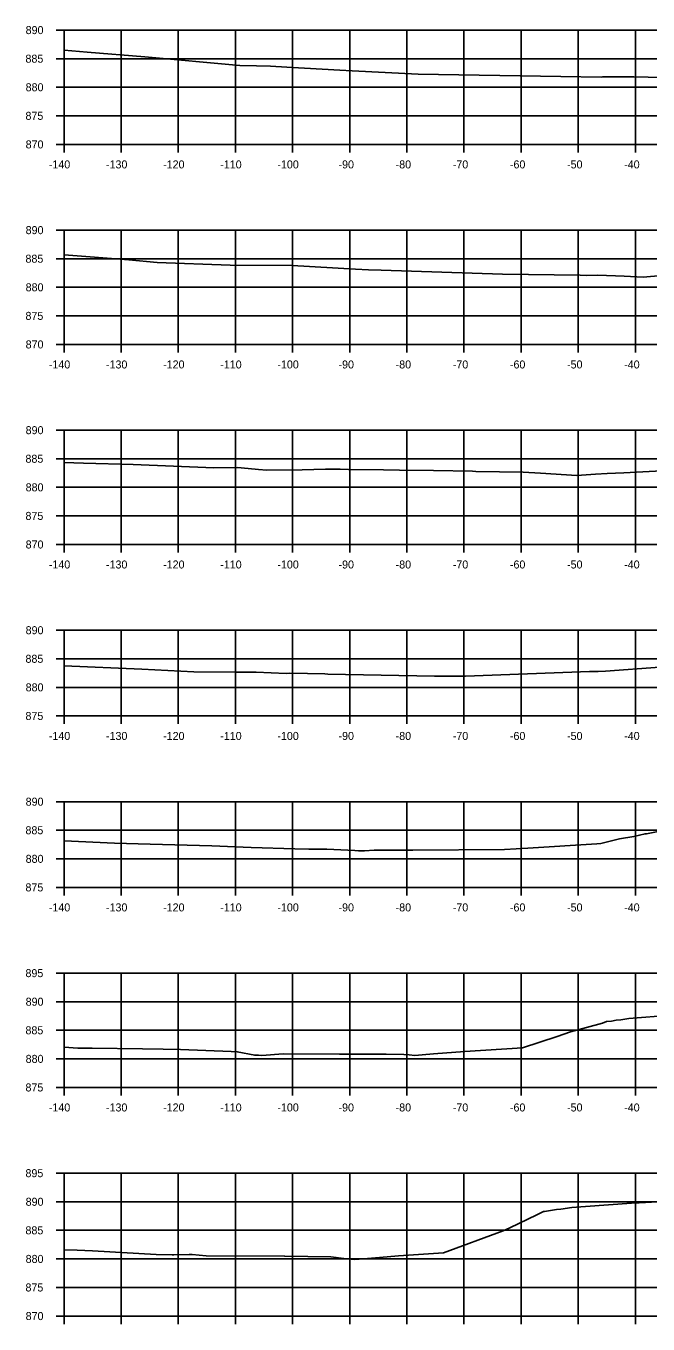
# Model space of a CAD drawing. Extents: x 1098669 to 1198896, y 698679 to 704410.
# Drawn here: x 1112162.5 to 1112271.4, y 701683.9 to 701911 of the extents above; entities that cross this region are included whole.
import ezdxf

# ---------------------------------------------------------------- set-up
doc = ezdxf.new("R2010")
doc.units = 0
for name, color, linetype in [('Proposed Surface', 7, 'Continuous'), ('R_Axis', 7, 'Continuous'), ('R_Axis Annot', 7, 'Continuous'), ('R_Grid', 7, 'Continuous')]:
    doc.layers.add(name, color=color, linetype=linetype)

msp = doc.modelspace()

# ---------------------------------------------------------------- linework, layer by layer
at = {"layer": 'Proposed Surface'}
for points in [[(1112169.18, 701906.73), (1112173.24, 701906.38), (1112183.35, 701905.57), (1112199.92, 701904.09), (1112202.88, 701903.99), (1112205.34, 701903.97), (1112208.19, 701903.8), (1112217.46, 701903.25), (1112219.61, 701903.12), (1112231.16, 701902.54), (1112256.16, 701902.15), (1112263.21, 701902.05), (1112263.45, 701902.06), (1112265.46, 701902.08), (1112268.41, 701902.11), (1112268.88, 701902.1), (1112273.92, 701901.95)], [(1112169.18, 701870.95), (1112180.51, 701870.04), (1112185.47, 701869.59), (1112198.24, 701869.14), (1112209.08, 701869.07), (1112220.21, 701868.42), (1112222.44, 701868.33), (1112224.69, 701868.27), (1112245.9, 701867.58), (1112259.5, 701867.37), (1112260.68, 701867.35), (1112262.58, 701867.38), (1112267.23, 701867.2), (1112270.55, 701867.06), (1112273.81, 701867.31)], [(1112169.18, 701834.59), (1112172.61, 701834.5), (1112181.25, 701834.23), (1112195.39, 701833.68), (1112199.52, 701833.75), (1112200.16, 701833.67), (1112203.22, 701833.4), (1112204.7, 701833.29), (1112210.83, 701833.34), (1112214.92, 701833.44), (1112217.49, 701833.41), (1112218.96, 701833.39), (1112225.12, 701833.32), (1112227.88, 701833.27), (1112233.87, 701833.2), (1112240.67, 701833.08), (1112241.27, 701833.05), (1112249.52, 701832.91), (1112252.57, 701832.74), (1112258.96, 701832.33), (1112262.22, 701832.57), (1112264.23, 701832.69), (1112267.17, 701832.8), (1112273.82, 701833.12)], [(1112169.18, 701799.04), (1112182.77, 701798.46), (1112189.63, 701798.1), (1112191.91, 701797.99), (1112199.1, 701797.93), (1112202.82, 701797.91), (1112208.04, 701797.71), (1112208.65, 701797.74), (1112211.82, 701797.67), (1112214.8, 701797.63), (1112215.37, 701797.59), (1112234.01, 701797.22), (1112239.45, 701797.23), (1112261.15, 701798.02), (1112262.64, 701798.03), (1112263.95, 701798.09), (1112273.46, 701798.77)], [(1112169.18, 701768.39), (1112178.04, 701767.98), (1112184.27, 701767.8), (1112195.07, 701767.52), (1112201.93, 701767.27), (1112209.6, 701767), (1112212.02, 701766.95), (1112215.16, 701766.96), (1112220.05, 701766.71), (1112220.74, 701766.64), (1112221.79, 701766.67), (1112223.44, 701766.78), (1112230.24, 701766.76), (1112246.3, 701766.9), (1112250.37, 701767.13), (1112262.41, 701767.91), (1112263.12, 701767.96), (1112266.41, 701768.73), (1112268.89, 701769.19), (1112270.89, 701769.65), (1112271.11, 701769.66), (1112275.15, 701770.45)], [(1112169.18, 701732.3), (1112171.62, 701732.15), (1112174.12, 701732.11), (1112182.91, 701732.02), (1112186.51, 701731.98), (1112189.54, 701731.9), (1112198.42, 701731.55), (1112199.49, 701731.51), (1112202.56, 701730.88), (1112203.19, 701730.89), (1112203.77, 701730.86), (1112207.54, 701731.12), (1112217.4, 701731.1), (1112223.28, 701731.11), (1112225.57, 701731.09), (1112228.66, 701731.04), (1112229.56, 701730.96), (1112230.56, 701730.84), (1112231.87, 701730.96), (1112233.85, 701731.15), (1112239.35, 701731.52), (1112249.41, 701732.17), (1112255.47, 701734.16), (1112257.83, 701735), (1112263.4, 701736.53), (1112264.13, 701736.8), (1112265, 701736.86), (1112265.8, 701737.01), (1112266.62, 701737.09), (1112268.06, 701737.31), (1112275.43, 701737.92)], [(1112169.18, 701696.86), (1112171.48, 701696.79), (1112174.16, 701696.65), (1112185.31, 701696.03), (1112188.12, 701695.99), (1112188.23, 701696), (1112188.37, 701696), (1112191.1, 701696.03), (1112191.57, 701696.04), (1112191.59, 701696.04), (1112191.63, 701696.03), (1112194.03, 701695.82), (1112207.78, 701695.76), (1112207.8, 701695.76), (1112207.82, 701695.76), (1112215.89, 701695.64), (1112218.18, 701695.31), (1112220.09, 701695.13), (1112221.6, 701695.25), (1112224.37, 701695.48), (1112227.7, 701695.8), (1112235.6, 701696.3), (1112246.02, 701700.19), (1112247.21, 701700.67), (1112251.91, 701702.97), (1112253.07, 701703.55), (1112253.27, 701703.58), (1112255.35, 701703.88), (1112256.11, 701703.98), (1112258.06, 701704.28), (1112260.45, 701704.44), (1112268.48, 701705), (1112269.82, 701705.06), (1112278.52, 701705.56)]]:
    msp.add_lwpolyline(points, dxfattribs=at)
at = {"layer": 'R_Axis'}
for p, q in [((1112167.78, 701910.26), (1112169.18, 701910.26)), ((1112169.18, 701890.26), (1112169.18, 701910.26)), ((1112167.78, 701905.26), (1112169.18, 701905.26)), ((1112167.78, 701900.26), (1112169.18, 701900.26)), ((1112167.78, 701895.26), (1112169.18, 701895.26)), ((1112167.78, 701890.26), (1112169.18, 701890.26)), ((1112169.18, 701890.26), (1112449.18, 701890.26)), ((1112169.18, 701888.86), (1112169.18, 701890.26)), ((1112179.18, 701888.86), (1112179.18, 701890.26)), ((1112189.18, 701888.86), (1112189.18, 701890.26)), ((1112199.18, 701888.86), (1112199.18, 701890.26)), ((1112209.18, 701888.86), (1112209.18, 701890.26)), ((1112219.18, 701888.86), (1112219.18, 701890.26)), ((1112229.18, 701888.86), (1112229.18, 701890.26)), ((1112239.18, 701888.86), (1112239.18, 701890.26)), ((1112249.18, 701888.86), (1112249.18, 701890.26)), ((1112259.18, 701888.86), (1112259.18, 701890.26)), ((1112269.18, 701888.86), (1112269.18, 701890.26)), ((1112167.78, 701875.26), (1112169.18, 701875.26)), ((1112169.18, 701855.26), (1112169.18, 701875.26)), ((1112167.78, 701870.26), (1112169.18, 701870.26)), ((1112167.78, 701865.26), (1112169.18, 701865.26)), ((1112167.78, 701860.26), (1112169.18, 701860.26)), ((1112167.78, 701855.26), (1112169.18, 701855.26)), ((1112169.18, 701855.26), (1112449.18, 701855.26)), ((1112169.18, 701853.86), (1112169.18, 701855.26)), ((1112179.18, 701853.86), (1112179.18, 701855.26)), ((1112189.18, 701853.86), (1112189.18, 701855.26)), ((1112199.18, 701853.86), (1112199.18, 701855.26)), ((1112209.18, 701853.86), (1112209.18, 701855.26)), ((1112219.18, 701853.86), (1112219.18, 701855.26)), ((1112229.18, 701853.86), (1112229.18, 701855.26)), ((1112239.18, 701853.86), (1112239.18, 701855.26)), ((1112249.18, 701853.86), (1112249.18, 701855.26)), ((1112259.18, 701853.86), (1112259.18, 701855.26)), ((1112269.18, 701853.86), (1112269.18, 701855.26)), ((1112167.78, 701840.26), (1112169.18, 701840.26)), ((1112169.18, 701820.26), (1112169.18, 701840.26)), ((1112167.78, 701835.26), (1112169.18, 701835.26)), ((1112167.78, 701830.26), (1112169.18, 701830.26)), ((1112167.78, 701825.26), (1112169.18, 701825.26)), ((1112167.78, 701820.26), (1112169.18, 701820.26)), ((1112169.18, 701820.26), (1112449.18, 701820.26)), ((1112169.18, 701818.86), (1112169.18, 701820.26)), ((1112179.18, 701818.86), (1112179.18, 701820.26)), ((1112189.18, 701818.86), (1112189.18, 701820.26)), ((1112199.18, 701818.86), (1112199.18, 701820.26)), ((1112209.18, 701818.86), (1112209.18, 701820.26)), ((1112219.18, 701818.86), (1112219.18, 701820.26)), ((1112229.18, 701818.86), (1112229.18, 701820.26)), ((1112239.18, 701818.86), (1112239.18, 701820.26)), ((1112249.18, 701818.86), (1112249.18, 701820.26)), ((1112259.18, 701818.86), (1112259.18, 701820.26)), ((1112269.18, 701818.86), (1112269.18, 701820.26)), ((1112167.78, 701805.26), (1112169.18, 701805.26)), ((1112169.18, 701790.26), (1112169.18, 701805.26)), ((1112167.78, 701800.26), (1112169.18, 701800.26)), ((1112167.78, 701795.26), (1112169.18, 701795.26)), ((1112167.78, 701790.26), (1112169.18, 701790.26)), ((1112169.18, 701790.26), (1112449.18, 701790.26)), ((1112169.18, 701788.86), (1112169.18, 701790.26)), ((1112179.18, 701788.86), (1112179.18, 701790.26)), ((1112189.18, 701788.86), (1112189.18, 701790.26)), ((1112199.18, 701788.86), (1112199.18, 701790.26)), ((1112209.18, 701788.86), (1112209.18, 701790.26)), ((1112219.18, 701788.86), (1112219.18, 701790.26)), ((1112229.18, 701788.86), (1112229.18, 701790.26)), ((1112239.18, 701788.86), (1112239.18, 701790.26)), ((1112249.18, 701788.86), (1112249.18, 701790.26)), ((1112259.18, 701788.86), (1112259.18, 701790.26)), ((1112269.18, 701788.86), (1112269.18, 701790.26)), ((1112167.78, 701775.26), (1112169.18, 701775.26)), ((1112169.18, 701760.26), (1112169.18, 701775.26)), ((1112167.78, 701770.26), (1112169.18, 701770.26)), ((1112167.78, 701765.26), (1112169.18, 701765.26)), ((1112167.78, 701760.26), (1112169.18, 701760.26)), ((1112169.18, 701760.26), (1112449.18, 701760.26)), ((1112169.18, 701758.86), (1112169.18, 701760.26)), ((1112179.18, 701758.86), (1112179.18, 701760.26)), ((1112189.18, 701758.86), (1112189.18, 701760.26)), ((1112199.18, 701758.86), (1112199.18, 701760.26)), ((1112209.18, 701758.86), (1112209.18, 701760.26)), ((1112219.18, 701758.86), (1112219.18, 701760.26)), ((1112229.18, 701758.86), (1112229.18, 701760.26)), ((1112239.18, 701758.86), (1112239.18, 701760.26)), ((1112249.18, 701758.86), (1112249.18, 701760.26)), ((1112259.18, 701758.86), (1112259.18, 701760.26)), ((1112269.18, 701758.86), (1112269.18, 701760.26)), ((1112167.78, 701745.26), (1112169.18, 701745.26)), ((1112169.18, 701725.26), (1112169.18, 701745.26)), ((1112167.78, 701740.26), (1112169.18, 701740.26)), ((1112167.78, 701735.26), (1112169.18, 701735.26)), ((1112167.78, 701730.26), (1112169.18, 701730.26)), ((1112167.78, 701725.26), (1112169.18, 701725.26)), ((1112169.18, 701725.26), (1112449.18, 701725.26)), ((1112169.18, 701723.86), (1112169.18, 701725.26)), ((1112179.18, 701723.86), (1112179.18, 701725.26)), ((1112189.18, 701723.86), (1112189.18, 701725.26)), ((1112199.18, 701723.86), (1112199.18, 701725.26)), ((1112209.18, 701723.86), (1112209.18, 701725.26)), ((1112219.18, 701723.86), (1112219.18, 701725.26)), ((1112229.18, 701723.86), (1112229.18, 701725.26)), ((1112239.18, 701723.86), (1112239.18, 701725.26)), ((1112249.18, 701723.86), (1112249.18, 701725.26)), ((1112259.18, 701723.86), (1112259.18, 701725.26)), ((1112269.18, 701723.86), (1112269.18, 701725.26)), ((1112167.78, 701710.26), (1112169.18, 701710.26)), ((1112169.18, 701685.26), (1112169.18, 701710.26)), ((1112167.78, 701705.26), (1112169.18, 701705.26)), ((1112167.78, 701700.26), (1112169.18, 701700.26)), ((1112167.78, 701695.26), (1112169.18, 701695.26)), ((1112167.78, 701690.26), (1112169.18, 701690.26)), ((1112167.78, 701685.26), (1112169.18, 701685.26)), ((1112169.18, 701685.26), (1112449.18, 701685.26)), ((1112169.18, 701683.86), (1112169.18, 701685.26)), ((1112179.18, 701683.86), (1112179.18, 701685.26)), ((1112189.18, 701683.86), (1112189.18, 701685.26)), ((1112199.18, 701683.86), (1112199.18, 701685.26)), ((1112209.18, 701683.86), (1112209.18, 701685.26)), ((1112219.18, 701683.86), (1112219.18, 701685.26)), ((1112229.18, 701683.86), (1112229.18, 701685.26)), ((1112239.18, 701683.86), (1112239.18, 701685.26)), ((1112249.18, 701683.86), (1112249.18, 701685.26)), ((1112259.18, 701683.86), (1112259.18, 701685.26)), ((1112269.18, 701683.86), (1112269.18, 701685.26))]:
    msp.add_line(p, q, dxfattribs=at)
at = {"layer": 'R_Grid'}
for p, q in [((1112169.18, 701910.26), (1112449.18, 701910.26)), ((1112169.18, 701890.26), (1112169.18, 701910.26)), ((1112179.18, 701890.26), (1112179.18, 701910.26)), ((1112189.18, 701890.26), (1112189.18, 701910.26)), ((1112199.18, 701890.26), (1112199.18, 701910.26)), ((1112209.18, 701890.26), (1112209.18, 701910.26)), ((1112219.18, 701890.26), (1112219.18, 701910.26)), ((1112229.18, 701890.26), (1112229.18, 701910.26)), ((1112239.18, 701890.26), (1112239.18, 701910.26)), ((1112249.18, 701890.26), (1112249.18, 701910.26)), ((1112259.18, 701890.26), (1112259.18, 701910.26)), ((1112269.18, 701890.26), (1112269.18, 701910.26)), ((1112169.18, 701905.26), (1112449.18, 701905.26)), ((1112169.18, 701900.26), (1112449.18, 701900.26)), ((1112169.18, 701895.26), (1112449.18, 701895.26)), ((1112169.18, 701890.26), (1112449.18, 701890.26)), ((1112169.18, 701875.26), (1112449.18, 701875.26)), ((1112169.18, 701855.26), (1112169.18, 701875.26)), ((1112179.18, 701855.26), (1112179.18, 701875.26)), ((1112189.18, 701855.26), (1112189.18, 701875.26)), ((1112199.18, 701855.26), (1112199.18, 701875.26)), ((1112209.18, 701855.26), (1112209.18, 701875.26)), ((1112219.18, 701855.26), (1112219.18, 701875.26)), ((1112229.18, 701855.26), (1112229.18, 701875.26)), ((1112239.18, 701855.26), (1112239.18, 701875.26)), ((1112249.18, 701855.26), (1112249.18, 701875.26)), ((1112259.18, 701855.26), (1112259.18, 701875.26)), ((1112269.18, 701855.26), (1112269.18, 701875.26)), ((1112169.18, 701870.26), (1112449.18, 701870.26)), ((1112169.18, 701865.26), (1112449.18, 701865.26)), ((1112169.18, 701860.26), (1112449.18, 701860.26)), ((1112169.18, 701855.26), (1112449.18, 701855.26)), ((1112169.18, 701840.26), (1112449.18, 701840.26)), ((1112169.18, 701820.26), (1112169.18, 701840.26)), ((1112179.18, 701820.26), (1112179.18, 701840.26)), ((1112189.18, 701820.26), (1112189.18, 701840.26)), ((1112199.18, 701820.26), (1112199.18, 701840.26)), ((1112209.18, 701820.26), (1112209.18, 701840.26)), ((1112219.18, 701820.26), (1112219.18, 701840.26)), ((1112229.18, 701820.26), (1112229.18, 701840.26)), ((1112239.18, 701820.26), (1112239.18, 701840.26)), ((1112249.18, 701820.26), (1112249.18, 701840.26)), ((1112259.18, 701820.26), (1112259.18, 701840.26)), ((1112269.18, 701820.26), (1112269.18, 701840.26)), ((1112169.18, 701835.26), (1112449.18, 701835.26)), ((1112169.18, 701830.26), (1112449.18, 701830.26)), ((1112169.18, 701825.26), (1112449.18, 701825.26)), ((1112169.18, 701820.26), (1112449.18, 701820.26)), ((1112169.18, 701805.26), (1112449.18, 701805.26)), ((1112169.18, 701790.26), (1112169.18, 701805.26)), ((1112179.18, 701790.26), (1112179.18, 701805.26)), ((1112189.18, 701790.26), (1112189.18, 701805.26)), ((1112199.18, 701790.26), (1112199.18, 701805.26)), ((1112209.18, 701790.26), (1112209.18, 701805.26)), ((1112219.18, 701790.26), (1112219.18, 701805.26)), ((1112229.18, 701790.26), (1112229.18, 701805.26)), ((1112239.18, 701790.26), (1112239.18, 701805.26)), ((1112249.18, 701790.26), (1112249.18, 701805.26)), ((1112259.18, 701790.26), (1112259.18, 701805.26)), ((1112269.18, 701790.26), (1112269.18, 701805.26)), ((1112169.18, 701800.26), (1112449.18, 701800.26)), ((1112169.18, 701795.26), (1112449.18, 701795.26)), ((1112169.18, 701790.26), (1112449.18, 701790.26)), ((1112169.18, 701775.26), (1112449.18, 701775.26)), ((1112169.18, 701760.26), (1112169.18, 701775.26)), ((1112179.18, 701760.26), (1112179.18, 701775.26)), ((1112189.18, 701760.26), (1112189.18, 701775.26)), ((1112199.18, 701760.26), (1112199.18, 701775.26)), ((1112209.18, 701760.26), (1112209.18, 701775.26)), ((1112219.18, 701760.26), (1112219.18, 701775.26)), ((1112229.18, 701760.26), (1112229.18, 701775.26)), ((1112239.18, 701760.26), (1112239.18, 701775.26)), ((1112249.18, 701760.26), (1112249.18, 701775.26)), ((1112259.18, 701760.26), (1112259.18, 701775.26)), ((1112269.18, 701760.26), (1112269.18, 701775.26)), ((1112169.18, 701770.26), (1112449.18, 701770.26)), ((1112169.18, 701765.26), (1112449.18, 701765.26)), ((1112169.18, 701760.26), (1112449.18, 701760.26)), ((1112169.18, 701745.26), (1112449.18, 701745.26)), ((1112169.18, 701725.26), (1112169.18, 701745.26)), ((1112179.18, 701725.26), (1112179.18, 701745.26)), ((1112189.18, 701725.26), (1112189.18, 701745.26)), ((1112199.18, 701725.26), (1112199.18, 701745.26)), ((1112209.18, 701725.26), (1112209.18, 701745.26)), ((1112219.18, 701725.26), (1112219.18, 701745.26)), ((1112229.18, 701725.26), (1112229.18, 701745.26)), ((1112239.18, 701725.26), (1112239.18, 701745.26)), ((1112249.18, 701725.26), (1112249.18, 701745.26)), ((1112259.18, 701725.26), (1112259.18, 701745.26)), ((1112269.18, 701725.26), (1112269.18, 701745.26)), ((1112169.18, 701740.26), (1112449.18, 701740.26)), ((1112169.18, 701735.26), (1112449.18, 701735.26)), ((1112169.18, 701730.26), (1112449.18, 701730.26)), ((1112169.18, 701725.26), (1112449.18, 701725.26)), ((1112169.18, 701710.26), (1112449.18, 701710.26)), ((1112169.18, 701685.26), (1112169.18, 701710.26)), ((1112179.18, 701685.26), (1112179.18, 701710.26)), ((1112189.18, 701685.26), (1112189.18, 701710.26)), ((1112199.18, 701685.26), (1112199.18, 701710.26)), ((1112209.18, 701685.26), (1112209.18, 701710.26)), ((1112219.18, 701685.26), (1112219.18, 701710.26)), ((1112229.18, 701685.26), (1112229.18, 701710.26)), ((1112239.18, 701685.26), (1112239.18, 701710.26)), ((1112249.18, 701685.26), (1112249.18, 701710.26)), ((1112259.18, 701685.26), (1112259.18, 701710.26)), ((1112269.18, 701685.26), (1112269.18, 701710.26)), ((1112169.18, 701705.26), (1112449.18, 701705.26)), ((1112169.18, 701700.26), (1112449.18, 701700.26)), ((1112169.18, 701695.26), (1112449.18, 701695.26)), ((1112169.18, 701690.26), (1112449.18, 701690.26)), ((1112169.18, 701685.26), (1112449.18, 701685.26))]:
    msp.add_line(p, q, dxfattribs=at)

# ---------------------------------------------------------------- texts
at = {"layer": 'R_Axis Annot'}
for s, p in [('890', (1112162.46, 701909.56)), ('885', (1112162.43, 701904.56)), ('880', (1112162.46, 701899.56)), ('875', (1112162.43, 701894.56)), ('870', (1112162.46, 701889.56)), ('-140', (1112166.52, 701886.06)), ('-130', (1112176.52, 701886.06)), ('-120', (1112186.52, 701886.06)), ('-110', (1112196.52, 701886.06)), ('-100', (1112206.52, 701886.06)), ('-90', (1112217.22, 701886.06)), ('-80', (1112227.22, 701886.06)), ('-70', (1112237.22, 701886.06)), ('-60', (1112247.22, 701886.06)), ('-50', (1112257.22, 701886.06)), ('-40', (1112267.22, 701886.06)), ('890', (1112162.46, 701874.56)), ('885', (1112162.43, 701869.56)), ('880', (1112162.46, 701864.56)), ('875', (1112162.43, 701859.56)), ('870', (1112162.46, 701854.56)), ('-140', (1112166.52, 701851.06)), ('-130', (1112176.52, 701851.06)), ('-120', (1112186.52, 701851.06)), ('-110', (1112196.52, 701851.06)), ('-100', (1112206.52, 701851.06)), ('-90', (1112217.22, 701851.06)), ('-80', (1112227.22, 701851.06)), ('-70', (1112237.22, 701851.06)), ('-60', (1112247.22, 701851.06)), ('-50', (1112257.22, 701851.06)), ('-40', (1112267.22, 701851.06)), ('890', (1112162.46, 701839.56)), ('885', (1112162.43, 701834.56)), ('880', (1112162.46, 701829.56)), ('875', (1112162.43, 701824.56)), ('870', (1112162.46, 701819.56)), ('-140', (1112166.52, 701816.06)), ('-130', (1112176.52, 701816.06)), ('-120', (1112186.52, 701816.06)), ('-110', (1112196.52, 701816.06)), ('-100', (1112206.52, 701816.06)), ('-90', (1112217.22, 701816.06)), ('-80', (1112227.22, 701816.06)), ('-70', (1112237.22, 701816.06)), ('-60', (1112247.22, 701816.06)), ('-50', (1112257.22, 701816.06)), ('-40', (1112267.22, 701816.06)), ('890', (1112162.46, 701804.56)), ('885', (1112162.43, 701799.56)), ('880', (1112162.46, 701794.56)), ('875', (1112162.43, 701789.56)), ('-140', (1112166.52, 701786.06)), ('-130', (1112176.52, 701786.06)), ('-120', (1112186.52, 701786.06)), ('-110', (1112196.52, 701786.06)), ('-100', (1112206.52, 701786.06)), ('-90', (1112217.22, 701786.06)), ('-80', (1112227.22, 701786.06)), ('-70', (1112237.22, 701786.06)), ('-60', (1112247.22, 701786.06)), ('-50', (1112257.22, 701786.06)), ('-40', (1112267.22, 701786.06)), ('890', (1112162.46, 701774.56)), ('885', (1112162.43, 701769.56)), ('880', (1112162.46, 701764.56)), ('875', (1112162.43, 701759.56)), ('-140', (1112166.52, 701756.06)), ('-130', (1112176.52, 701756.06)), ('-120', (1112186.52, 701756.06)), ('-110', (1112196.52, 701756.06)), ('-100', (1112206.52, 701756.06)), ('-90', (1112217.22, 701756.06)), ('-80', (1112227.22, 701756.06)), ('-70', (1112237.22, 701756.06)), ('-60', (1112247.22, 701756.06)), ('-50', (1112257.22, 701756.06)), ('-40', (1112267.22, 701756.06)), ('895', (1112162.43, 701744.56)), ('890', (1112162.46, 701739.56)), ('885', (1112162.43, 701734.56)), ('880', (1112162.46, 701729.56)), ('875', (1112162.43, 701724.56)), ('-140', (1112166.52, 701721.06)), ('-130', (1112176.52, 701721.06)), ('-120', (1112186.52, 701721.06)), ('-110', (1112196.52, 701721.06)), ('-100', (1112206.52, 701721.06)), ('-90', (1112217.22, 701721.06)), ('-80', (1112227.22, 701721.06)), ('-70', (1112237.22, 701721.06)), ('-60', (1112247.22, 701721.06)), ('-50', (1112257.22, 701721.06)), ('-40', (1112267.22, 701721.06)), ('895', (1112162.43, 701709.56)), ('890', (1112162.46, 701704.56)), ('885', (1112162.43, 701699.56)), ('880', (1112162.46, 701694.56)), ('875', (1112162.43, 701689.56)), ('870', (1112162.46, 701684.56))]:
    msp.add_text(s, height=1.4, dxfattribs=at).set_placement(p)

doc.saveas('drawing.dxf')
